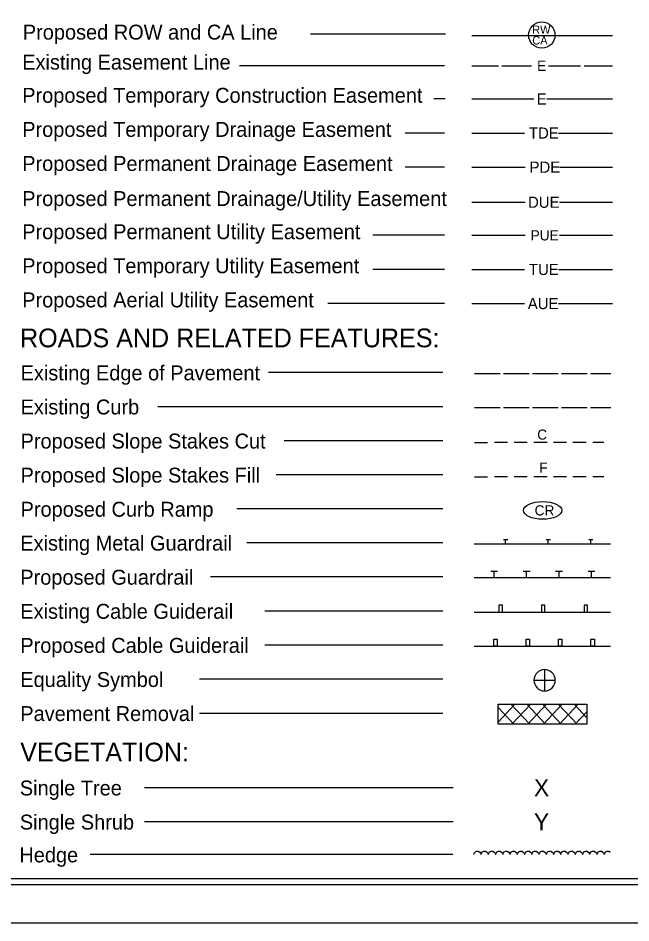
# Model space of a CAD drawing. Extents: x 925297 to 940193, y 663541 to 689899.
# Drawn here: x 929797 to 932672, y 663541 to 667786 of the extents above; entities that cross this region are included whole.
import ezdxf

# ---------------------------------------------------------------- set-up
doc = ezdxf.new("R2010")
doc.units = 0
for name, color, linetype in [('Default', 7, 'Continuous'), ('Sheet Cutting Line CELL', 7, 'Continuous'), ('Sheet Plot Border Inside CELL', 7, 'Continuous'), ('Sheet Plot Border Outside CELL', 7, 'Continuous'), ('Sheet Symbology CELL', 7, 'Continuous')]:
    doc.layers.add(name, color=color, linetype=linetype)

msp = doc.modelspace()

# ---------------------------------------------------------------- linework, layer by layer
at = {"layer": 'Default'}
for p, q in [((931925.8, 666922.5), (932176.1, 666922.5)), ((932336.1, 666922.5), (932585.6, 666922.5))]:
    msp.add_line(p, q, dxfattribs=at)
msp.add_ellipse((932257.7, 665476.4), major_axis=(89.7, 0), ratio=0.462467, dxfattribs=at)
at = {"layer": 'Sheet Cutting Line CELL'}
msp.add_line((925296.7, 663541.3), (938764.7, 663541.3), dxfattribs=at)
at = {"layer": 'Sheet Plot Border Inside CELL'}
msp.add_lwpolyline([(925400.7, 663720.9), (938728.7, 663720.9), (938728.7, 672159.2), (925400.7, 672159.2)], close=True, dxfattribs=at)
at = {"layer": 'Sheet Plot Border Outside CELL'}
msp.add_lwpolyline([(925296.7, 663541.3), (938764.7, 663541.3), (938764.7, 672338.7), (925296.7, 672338.7)], close=True, dxfattribs=at)
at = {"layer": 'Sheet Symbology CELL'}
for p, q in [((931802.7, 667711.5), (931168, 667711.5)), ((931925.9, 667705.3), (932585.7, 667705.3)), ((931797.6, 667562.6), (930835.6, 667562.6)), ((931925.8, 667562.6), (932049.9, 667562.6)), ((932065.9, 667562.6), (932205.8, 667562.6)), ((932285.8, 667562.6), (932435.7, 667562.6)), ((932451.7, 667562.6), (932585.6, 667562.6)), ((931800.7, 667407), (931747.3, 667407)), ((931925.8, 667407), (931946.7, 667407)), ((931946.7, 667407), (932216.6, 667407)), ((932276.6, 667407), (932546.5, 667407)), ((932546.5, 667407), (932585.6, 667407)), ((931797.6, 667247.1), (931612.5, 667247.1)), ((931925.8, 667247.1), (931952.6, 667247.1)), ((931952.6, 667247.1), (932172.5, 667247.1)), ((932332.5, 667247.1), (932552.4, 667247.1)), ((932552.4, 667247.1), (932585.6, 667247.1)), ((931797.6, 667087.1), (931612.5, 667087.1)), ((931925.8, 667087.1), (931956.2, 667087.1)), ((931956.2, 667087.1), (932176.1, 667087.1)), ((932336.1, 667087.1), (932556, 667087.1)), ((932556, 667087.1), (932585.6, 667087.1)), ((931797.6, 666767.1), (931460.6, 666767.1)), ((931925.8, 666767.1), (931956.5, 666767.1)), ((931956.5, 666767.1), (932176.4, 666767.1)), ((932336.4, 666767.1), (932556.3, 666767.1)), ((932556.3, 666767.1), (932585.6, 666767.1)), ((931797.6, 666607.2), (931460.6, 666607.2)), ((931925.8, 666607.2), (931952.6, 666607.2)), ((931952.6, 666607.2), (932172.5, 666607.2)), ((932332.5, 666607.2), (932552.4, 666607.2)), ((932552.4, 666607.2), (932585.6, 666607.2)), ((931797.6, 666447.2), (931250.1, 666447.2)), ((931925.8, 666447.2), (931952.6, 666447.2)), ((931952.6, 666447.2), (932172.5, 666447.2)), ((932332.5, 666447.2), (932552.4, 666447.2)), ((932552.4, 666447.2), (932585.6, 666447.2)), ((931789.9, 666123.1), (930971.3, 666123.1)), ((931938.1, 666118.5), (932058.1, 666118.5)), ((932074.1, 666118.5), (932194, 666118.5)), ((932210, 666118.5), (932330, 666118.5)), ((932346, 666118.5), (932465.9, 666118.5)), ((932481.9, 666118.5), (932577.9, 666118.5)), ((931789.9, 665963.2), (930453.1, 665963.2)), ((931938.1, 665958.6), (932058.1, 665958.6)), ((932074.1, 665958.6), (932194, 665958.6)), ((932210, 665958.6), (932330, 665958.6)), ((932346, 665958.6), (932465.9, 665958.6)), ((932481.9, 665958.6), (932577.9, 665958.6)), ((931789.9, 665803.2), (931044.6, 665803.2)), ((931938.1, 665794.8), (931998.9, 665794.8)), ((932092.5, 665794.8), (932032.1, 665794.8)), ((932184.4, 665794.8), (932123.6, 665794.8)), ((932278.4, 665794.8), (932216, 665794.8)), ((932370, 665794.8), (932308, 665794.8)), ((932462.3, 665794.8), (932399.6, 665794.8)), ((932544.7, 665794.8), (932493.5, 665794.8)), ((931789.9, 665643.2), (931008.2, 665643.2)), ((931938.1, 665634.8), (931998.9, 665634.8)), ((932092.5, 665634.8), (932032.1, 665634.8)), ((932184.4, 665634.8), (932123.6, 665634.8)), ((932278.4, 665634.8), (932216, 665634.8)), ((932370, 665634.8), (932308, 665634.8)), ((932462.3, 665634.8), (932399.6, 665634.8)), ((932544.7, 665634.8), (932493.5, 665634.8)), ((931789.9, 665483.3), (930822.8, 665483.3)), ((932073.9, 665339.7), (932093.9, 665339.7)), ((932083.9, 665319.7), (932083.9, 665339.7)), ((932273.8, 665339.7), (932293.8, 665339.7)), ((932283.8, 665319.7), (932283.8, 665339.7)), ((932473.8, 665339.7), (932493.8, 665339.7)), ((932483.8, 665319.7), (932483.8, 665339.7)), ((931788.7, 665324.3), (930870.2, 665324.3)), ((931936.8, 665319.7), (932576.7, 665319.7)), ((932014.6, 665191.3), (932046.6, 665191.3)), ((932030.6, 665159.7), (932030.6, 665191.3)), ((932166.6, 665191.3), (932198.6, 665191.3)), ((932182.6, 665159.7), (932182.6, 665191.3)), ((932318.5, 665191.3), (932350.5, 665191.3)), ((932334.5, 665159.7), (932334.5, 665191.3)), ((932470.5, 665191.3), (932502.5, 665191.3)), ((932486.5, 665159.7), (932486.5, 665191.3)), ((931788.7, 665164.3), (930699.1, 665164.3)), ((932576.7, 665159.7), (931936.8, 665159.7)), ((931788.7, 665004.4), (930954.5, 665004.4)), ((931936.8, 664999.8), (932576.7, 664999.8)), ((931788.7, 664844.4), (930954.5, 664844.4)), ((931936.8, 664839.8), (932576.7, 664839.8)), ((932266.5, 664729.8), (932266.5, 664679.8)), ((931788.7, 664684.5), (930648, 664684.5)), ((932216.6, 664679.8), (932266.5, 664679.8)), ((932266.5, 664679.8), (932266.5, 664629.8)), ((932266.5, 664679.8), (932316.5, 664679.8)), ((932048.4, 664566.8), (932465.1, 664566.8)), ((932048.4, 664473.3), (932048.4, 664566.8)), ((932048.4, 664562), (932052.8, 664566.8)), ((932048.4, 664482.5), (932127.2, 664566.8)), ((932122.4, 664473.3), (932048.4, 664552.4)), ((932196.8, 664473.3), (932108.8, 664566.8)), ((932113.6, 664473.3), (932201.6, 664566.8)), ((932270.7, 664473.3), (932183.2, 664566.8)), ((932187.6, 664473.3), (932275.9, 664566.8)), ((932345.1, 664473.3), (932257.2, 664566.8)), ((932262, 664473.3), (932349.9, 664566.8)), ((932419.5, 664473.3), (932331.1, 664566.8)), ((932336.3, 664473.3), (932423.9, 664566.8)), ((932465.1, 664503.2), (932405.5, 664566.8)), ((932410.3, 664473.3), (932465.1, 664531.6)), ((932465.1, 664566.8), (932465.1, 664473.3)), ((931788.7, 664524.5), (930648, 664524.5)), ((932465.1, 664473.3), (932048.4, 664473.3)), ((931837.7, 664175.5), (930389.2, 664175.5)), ((931837.7, 664015.5), (930389.2, 664015.5)), ((931835.6, 663861.5), (930134.6, 663861.5)), ((931934.7, 663861.5), (931937.1, 663869.1)), ((931937.1, 663869.1), (931941.9, 663874.3)), ((931941.9, 663874.3), (931948.3, 663877.9)), ((931948.3, 663877.9), (931955.9, 663877.9)), ((931955.9, 663877.9), (931962.3, 663873.9)), ((931962.3, 663873.9), (931966.7, 663868.7)), ((931966.7, 663868.7), (931968.3, 663861.9)), ((931968.7, 663861.5), (931971.1, 663869.1)), ((931971.1, 663869.1), (931975.9, 663874.3)), ((931975.9, 663874.3), (931982.3, 663877.9)), ((931982.3, 663877.9), (931989.9, 663877.9)), ((931989.9, 663877.9), (931996.3, 663873.9)), ((931996.3, 663873.9), (932000.7, 663868.7)), ((932000.7, 663868.7), (932002.3, 663861.9)), ((932002.7, 663861.5), (932005.1, 663869.1)), ((932005.1, 663869.1), (932009.9, 663874.3)), ((932009.9, 663874.3), (932016.3, 663877.9)), ((932016.3, 663877.9), (932023.9, 663877.9)), ((932023.9, 663877.9), (932030.3, 663873.9)), ((932030.3, 663873.9), (932034.7, 663868.7)), ((932034.7, 663868.7), (932036.3, 663861.9)), ((932036.7, 663861.5), (932039.1, 663869.1)), ((932039.1, 663869.1), (932043.9, 663874.3)), ((932043.9, 663874.3), (932050.3, 663877.9)), ((932050.3, 663877.9), (932057.9, 663877.9)), ((932057.9, 663877.9), (932064.3, 663873.9)), ((932064.3, 663873.9), (932068.7, 663868.7)), ((932068.7, 663868.7), (932070.3, 663861.9)), ((932070.7, 663861.5), (932073.1, 663869.1)), ((932073.1, 663869.1), (932077.9, 663874.3)), ((932077.9, 663874.3), (932084.3, 663877.9)), ((932084.3, 663877.9), (932091.9, 663877.9)), ((932091.9, 663877.9), (932098.3, 663873.9)), ((932098.3, 663873.9), (932102.7, 663868.7)), ((932102.7, 663868.7), (932104.3, 663861.9)), ((932104.7, 663861.5), (932107.1, 663869.1)), ((932107.1, 663869.1), (932111.9, 663874.3)), ((932111.9, 663874.3), (932118.2, 663877.9)), ((932118.2, 663877.9), (932125.8, 663877.9)), ((932125.8, 663877.9), (932132.2, 663873.9)), ((932132.2, 663873.9), (932136.6, 663868.7)), ((932136.6, 663868.7), (932138.2, 663861.9)), ((932138.6, 663861.5), (932141, 663869.1)), ((932141, 663869.1), (932145.8, 663874.3)), ((932145.8, 663874.3), (932152.2, 663877.9)), ((932152.2, 663877.9), (932159.8, 663877.9)), ((932159.8, 663877.9), (932166.2, 663873.9)), ((932166.2, 663873.9), (932170.6, 663868.7)), ((932170.6, 663868.7), (932172.2, 663861.9)), ((932172.6, 663861.5), (932175, 663869.1)), ((932175, 663869.1), (932179.8, 663874.3)), ((932179.8, 663874.3), (932186.2, 663877.9)), ((932186.2, 663877.9), (932193.8, 663877.9)), ((932193.8, 663877.9), (932200.2, 663873.9)), ((932200.2, 663873.9), (932204.6, 663868.7)), ((932204.6, 663868.7), (932206.2, 663861.9)), ((932206.6, 663861.5), (932209, 663869.1)), ((932209, 663869.1), (932213.8, 663874.3)), ((932213.8, 663874.3), (932220.2, 663877.9)), ((932220.2, 663877.9), (932227.8, 663877.9)), ((932227.8, 663877.9), (932234.2, 663873.9)), ((932234.2, 663873.9), (932238.6, 663868.7)), ((932238.6, 663868.7), (932240.2, 663861.9)), ((932240.6, 663861.5), (932243, 663869.1)), ((932243, 663869.1), (932247.8, 663874.3)), ((932247.8, 663874.3), (932254.2, 663877.9)), ((932254.2, 663877.9), (932261.8, 663877.9)), ((932261.8, 663877.9), (932268.2, 663873.9)), ((932268.2, 663873.9), (932272.6, 663868.7)), ((932272.6, 663868.7), (932274.2, 663861.9)), ((932274.6, 663861.5), (932277, 663869.1)), ((932277, 663869.1), (932281.8, 663874.3)), ((932281.8, 663874.3), (932288.2, 663877.9)), ((932288.2, 663877.9), (932295.8, 663877.9)), ((932295.8, 663877.9), (932302.2, 663873.9)), ((932302.2, 663873.9), (932306.6, 663868.7)), ((932306.6, 663868.7), (932308.2, 663861.9)), ((932308.6, 663861.5), (932311, 663869.1)), ((932311, 663869.1), (932315.8, 663874.3)), ((932315.8, 663874.3), (932322.2, 663877.9)), ((932322.2, 663877.9), (932329.8, 663877.9)), ((932329.8, 663877.9), (932336.2, 663873.9)), ((932336.2, 663873.9), (932340.6, 663868.7)), ((932340.6, 663868.7), (932342.2, 663861.9)), ((932342.6, 663861.5), (932345, 663869.1)), ((932345, 663869.1), (932349.8, 663874.3)), ((932349.8, 663874.3), (932356.2, 663877.9)), ((932356.2, 663877.9), (932363.8, 663877.9)), ((932363.8, 663877.9), (932370.2, 663873.9)), ((932370.2, 663873.9), (932374.6, 663868.7)), ((932374.6, 663868.7), (932376.2, 663861.9)), ((932376.6, 663861.5), (932379, 663869.1)), ((932379, 663869.1), (932383.8, 663874.3)), ((932383.8, 663874.3), (932390.2, 663877.9)), ((932390.2, 663877.9), (932397.8, 663877.9)), ((932397.8, 663877.9), (932404.2, 663873.9)), ((932404.2, 663873.9), (932408.6, 663868.7)), ((932408.6, 663868.7), (932410.2, 663861.9)), ((932410.6, 663861.5), (932413, 663869.1)), ((932413, 663869.1), (932417.8, 663874.3)), ((932417.8, 663874.3), (932424.2, 663877.9)), ((932424.2, 663877.9), (932431.8, 663877.9)), ((932431.8, 663877.9), (932438.2, 663873.9)), ((932438.2, 663873.9), (932442.6, 663868.7)), ((932442.6, 663868.7), (932444.2, 663861.9)), ((932444.6, 663861.5), (932447, 663869.1)), ((932447, 663869.1), (932451.8, 663874.3)), ((932451.8, 663874.3), (932458.1, 663877.9)), ((932458.1, 663877.9), (932465.7, 663877.9)), ((932465.7, 663877.9), (932472.1, 663873.9)), ((932472.1, 663873.9), (932476.5, 663868.7)), ((932476.5, 663868.7), (932478.1, 663861.9)), ((932478.5, 663861.5), (932480.9, 663869.1)), ((932480.9, 663869.1), (932485.7, 663874.3)), ((932485.7, 663874.3), (932492.1, 663877.9)), ((932492.1, 663877.9), (932499.7, 663877.9)), ((932499.7, 663877.9), (932506.1, 663873.9)), ((932506.1, 663873.9), (932510.5, 663868.7)), ((932510.5, 663868.7), (932512.1, 663861.9)), ((932512.5, 663861.5), (932514.9, 663869.1)), ((932514.9, 663869.1), (932519.7, 663874.3)), ((932519.7, 663874.3), (932526.1, 663877.9)), ((932526.1, 663877.9), (932533.7, 663877.9)), ((932533.7, 663877.9), (932540.1, 663873.9)), ((932540.1, 663873.9), (932544.5, 663868.7)), ((932544.5, 663868.7), (932546.1, 663861.9)), ((932546.5, 663861.5), (932548.9, 663869.1)), ((932548.9, 663869.1), (932553.7, 663874.3)), ((932553.7, 663874.3), (932560.1, 663877.9)), ((932560.1, 663877.9), (932567.7, 663877.9)), ((932567.7, 663877.9), (932574.1, 663873.9)), ((932574.1, 663873.9), (932574.5, 663873.5))]:
    msp.add_line(p, q, dxfattribs=at)
for points in [[(938628.7, 672138.8), (926632.3, 672138.8), (926632.3, 663749.4), (938628.7, 663749.4)], [(932052.6, 664999.8), (932068.6, 664999.8), (932068.6, 665031.8), (932052.6, 665031.8)], [(932252.6, 664999.8), (932268.5, 664999.8), (932268.5, 665031.8), (932252.6, 665031.8)], [(932452.5, 664999.8), (932468.5, 664999.8), (932468.5, 665031.8), (932452.5, 665031.8)], [(932028.5, 664871.8), (932044.5, 664871.8), (932044.5, 664839.8), (932028.5, 664839.8)], [(932180.5, 664871.8), (932196.5, 664871.8), (932196.5, 664839.8), (932180.5, 664839.8)], [(932332.4, 664871.8), (932348.4, 664871.8), (932348.4, 664839.8), (932332.4, 664839.8)], [(932484.4, 664871.8), (932500.4, 664871.8), (932500.4, 664839.8), (932484.4, 664839.8)]]:
    msp.add_lwpolyline(points, close=True, dxfattribs=at)
msp.add_circle((932253.7, 667706.5), 61.7, dxfattribs=at)
for start, end in [(89.9944, 179.9989), (359.9944, 89.9989), (179.9944, 269.9989), (269.9944, 359.9989)]:
    msp.add_arc((932266.6, 664679.8), 50, start, end, dxfattribs=at)

# ---------------------------------------------------------------- texts
at = {"layer": 'Default'}
for s, height, p in [('DUE', 52.38, (932188.9, 666896.1)), ('CR', 47.99, (932220, 665452.7))]:
    msp.add_text(s, height=height, dxfattribs=at).set_placement(p)
at = {"layer": 'Sheet Symbology CELL'}
for s, height, p in [('Proposed ROW and CA Line', 69.979, (929819.1, 667685.3)), ('RW', 38.7, (932208.3, 667712.7)), ('CA', 38.7, (932208.9, 667662.4)), ('Existing Easement Line', 69.979, (929816.2, 667544.5)), ('E', 48, (932231.4, 667538.6)), ('Proposed Temporary Construction Easement', 69.979, (929816.2, 667388.9)), ('E', 52.4, (932229.4, 667380.6)), ('Proposed Temporary Drainage Easement', 69.979, (929816.2, 667229)), ('TDE', 52.38, (932193.3, 667220.7)), ('Proposed Permanent Drainage Easement', 69.979, (929816.2, 667069)), ('PDE', 52.38, (932196.1, 667060.7)), ('Proposed Permanent Drainage/Utility Easement', 69.979, (929816.2, 666904.4)), ('Proposed Permanent Utility Easement', 69.979, (929816.2, 666749)), ('PUE', 47.99, (932201.2, 666743.1)), ('Proposed Temporary Utility Easement', 69.979, (929816.2, 666589.1)), ('TUE', 52.38, (932193.2, 666580.8)), ('Proposed Aerial Utility Easement', 69.979, (929816.2, 666429.1)), ('AUE', 52.38, (932187.9, 666420.8)), ('ROADS AND RELATED FEATURES:', 87.974, (929806.1, 666241.8)), ('Existing Edge of Pavement', 69.979, (929808.5, 666086.7)), ('Existing Curb', 69.979, (929808.5, 665926.8)), ('C', 47.4, (932232.4, 665808.7)), ('Proposed Slope Stakes Cut', 69.979, (929808.5, 665766.8)), ('Proposed Slope Stakes Fill', 69.979, (929808.5, 665606.9)), ('F', 47.4, (932242, 665653.7)), ('Proposed Curb Ramp', 69.979, (929808.5, 665446.9)), ('Existing Metal Guardrail', 69.979, (929807.2, 665287.9)), ('Proposed Guardrail', 69.979, (929807.3, 665128.1)), ('Existing Cable Guiderail', 69.979, (929807.3, 664968.1)), ('Proposed Cable Guiderail', 69.979, (929807.3, 664808.2)), ('Equality Symbol', 69.979, (929807.3, 664648.2)), ('Pavement Removal', 69.979, (929807.3, 664488.2)), ('VEGETATION:', 87.974, (929807.2, 664299)), ('Single Tree', 69.979, (929805, 664139.3)), ('X', 80, (932216.8, 664135.5)), ('Single Shrub', 69.979, (929805, 663979.3)), ('Y', 80, (932216.8, 663975.5)), ('Hedge', 69.98, (929802.9, 663825.3))]:
    msp.add_text(s, height=height, dxfattribs=at).set_placement(p)

doc.saveas('drawing.dxf')
